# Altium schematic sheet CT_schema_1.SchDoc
size 515 x 464 mm
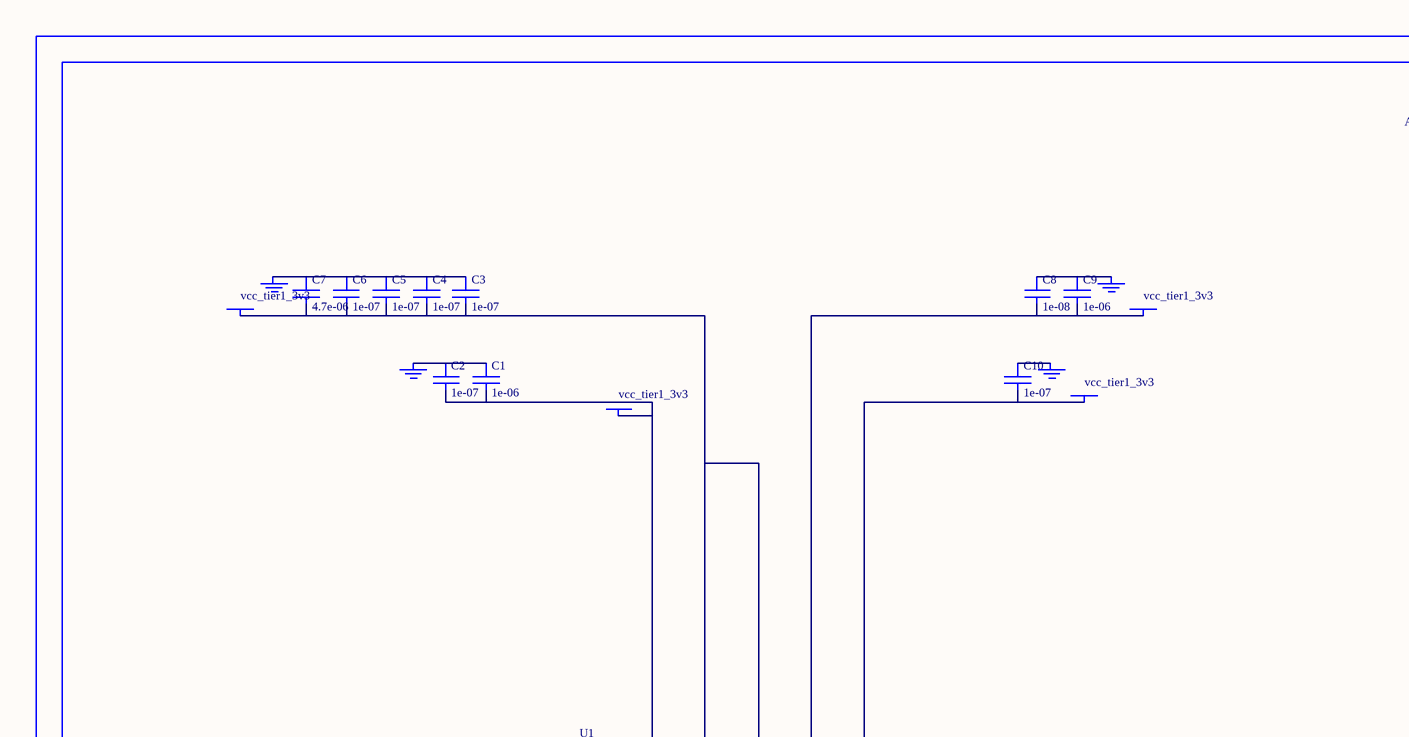
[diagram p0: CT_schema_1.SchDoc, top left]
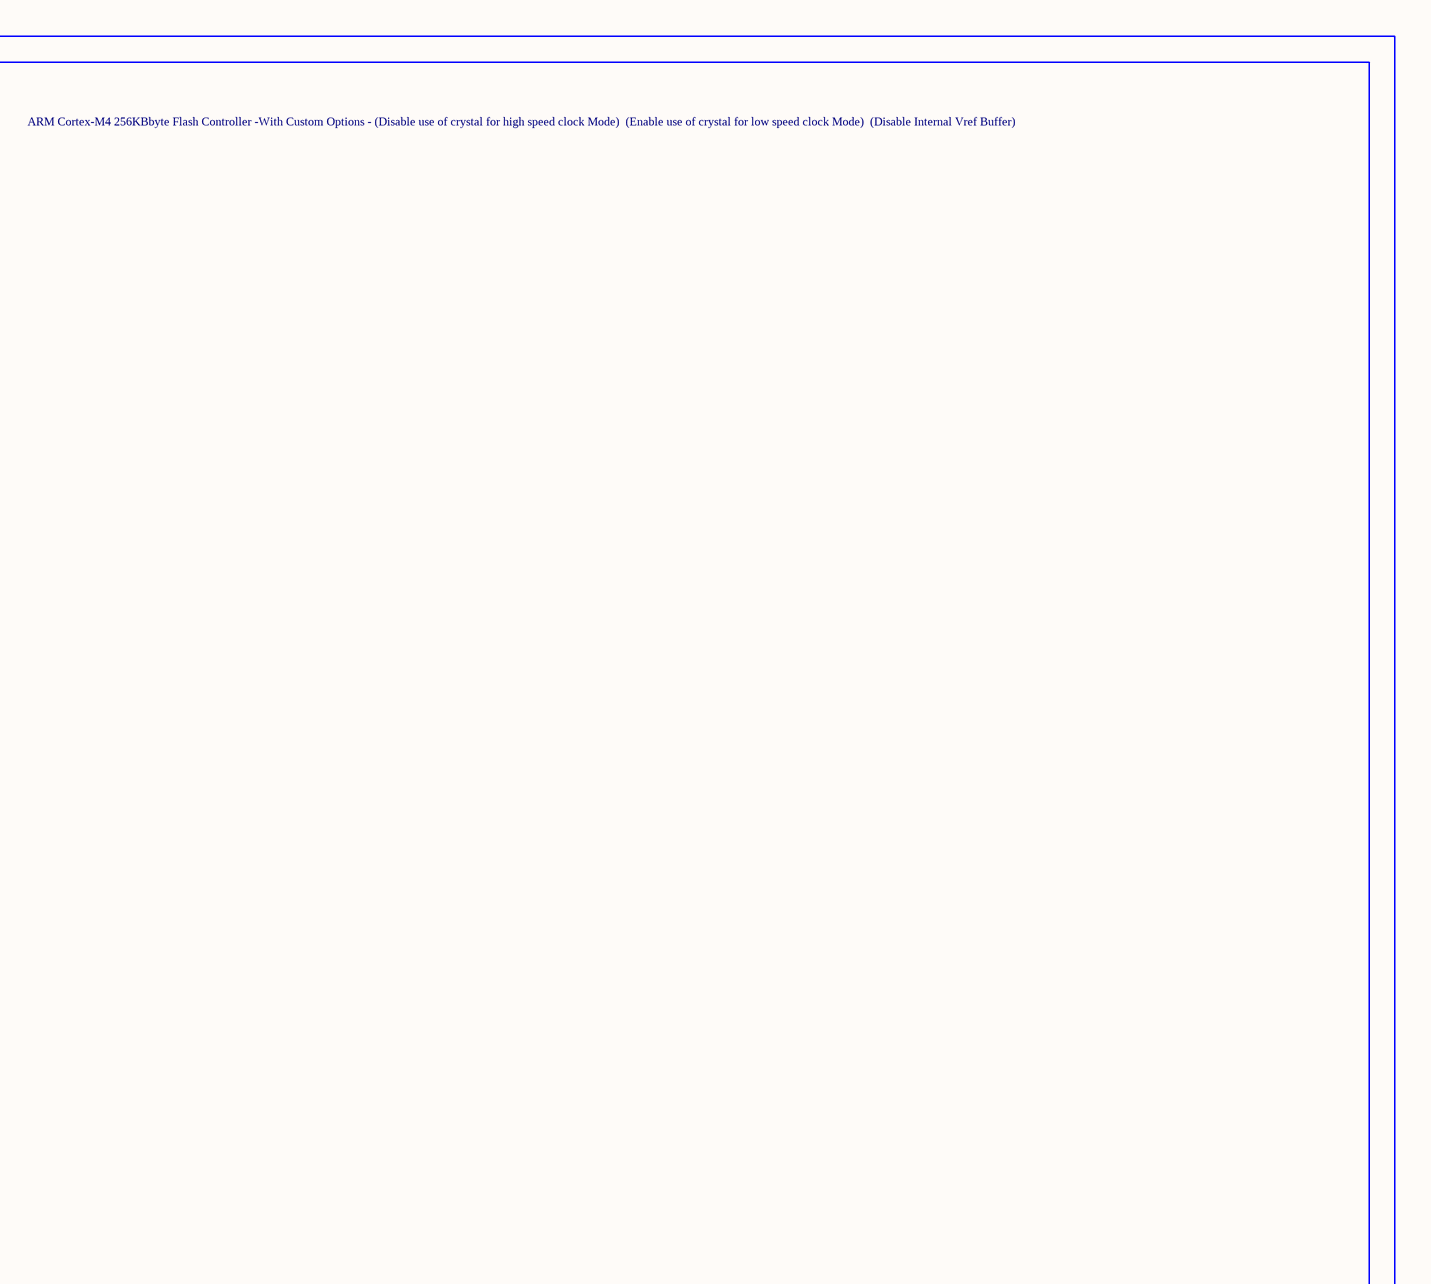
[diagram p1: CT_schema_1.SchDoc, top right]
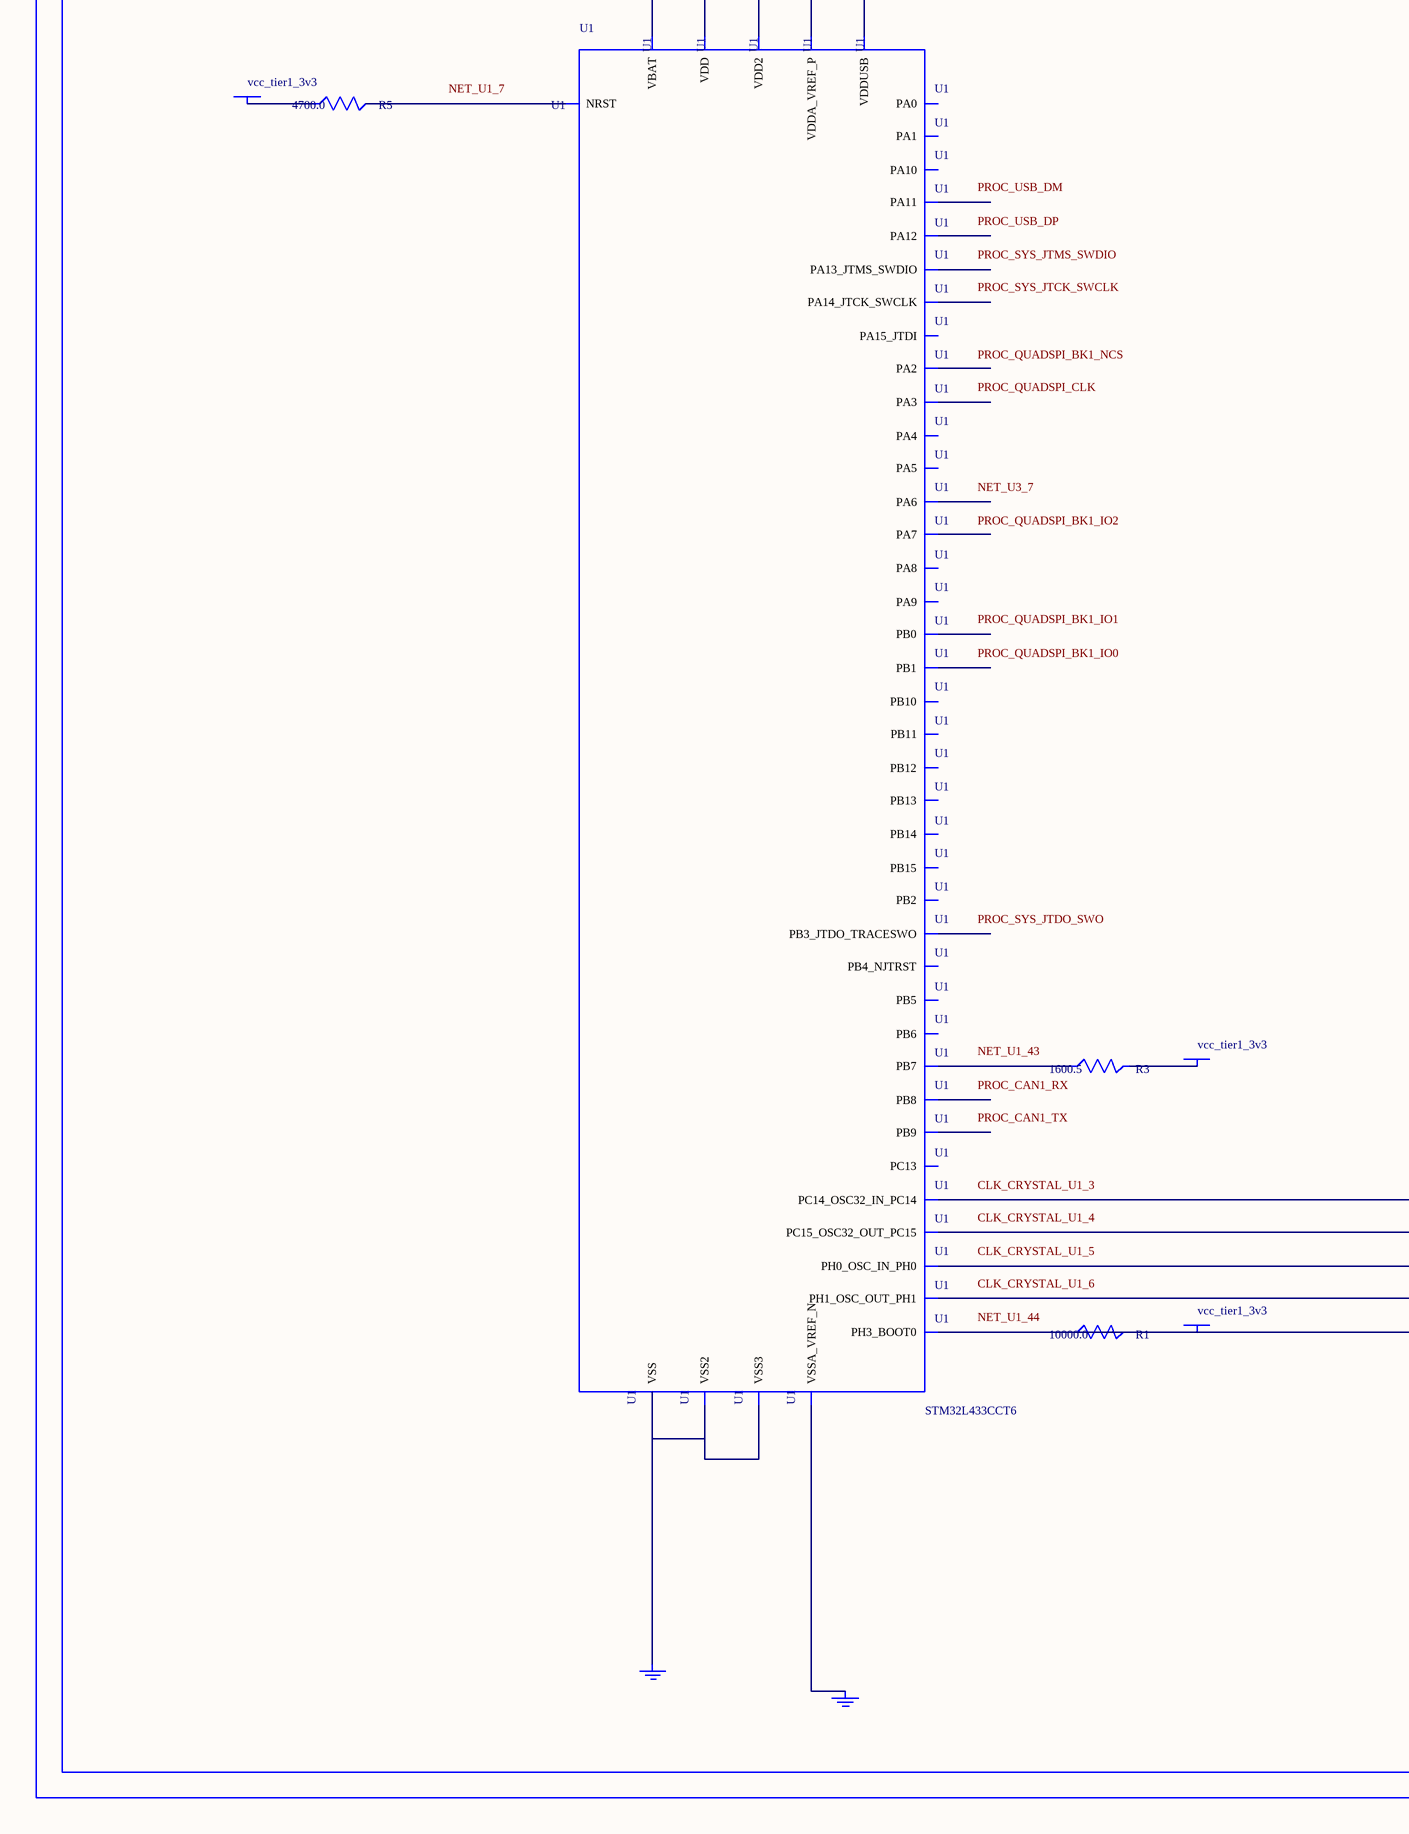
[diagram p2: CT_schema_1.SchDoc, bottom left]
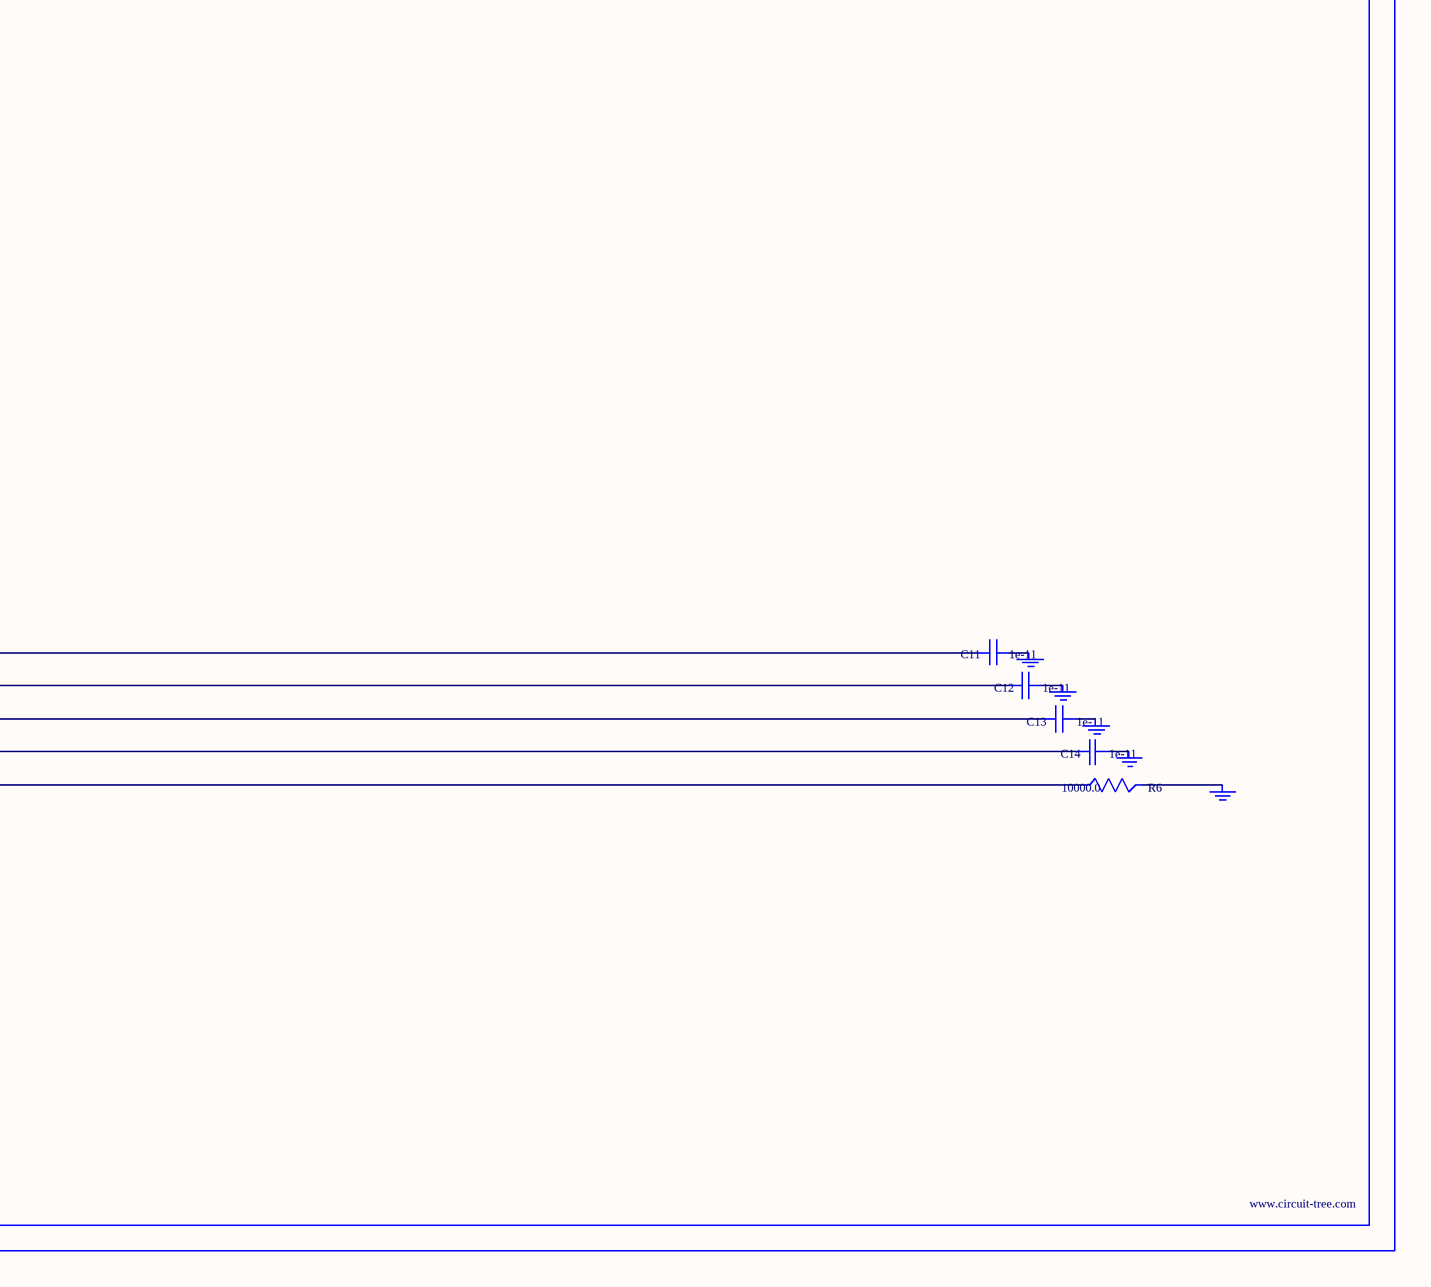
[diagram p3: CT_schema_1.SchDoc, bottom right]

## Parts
BORDER0  (no value)
C1  1e-06  [C0603]
C2  1e-07  [C0603]
C3  1e-07  [C0603]
C4  1e-07  [C0603]
C5  1e-07  [C0603]
C6  1e-07  [C0603]
C7  4.7e-06  [C0603]
C8  1e-08  [C0603]
C9  1e-06  [C0603]
C10  1e-07  [C0603]
C11  1e-11  [C0402]
C12  1e-11  [C0402]
C13  1e-11  [C0402]
C14  1e-11  [C0402]
GND_INSTANCE_0_0  (no value)
GND_INSTANCE_0_1  (no value)
GND_INSTANCE_0_2  (no value)
GND_INSTANCE_0_3  (no value)
GND_INSTANCE_0_4  (no value)
GND_INSTANCE_0_5  (no value)
GND_INSTANCE_0_6  (no value)
GND_INSTANCE_0_7  (no value)
GND_INSTANCE_0_8  (no value)
GND_INSTANCE_0_9  (no value)
GND_INSTANCE_0_10  (no value)
POWER_INSTANCE_0_0  vcc_tier1_3v3
POWER_INSTANCE_0_1  vcc_tier1_3v3
POWER_INSTANCE_0_2  vcc_tier1_3v3
POWER_INSTANCE_0_3  vcc_tier1_3v3
POWER_INSTANCE_0_4  vcc_tier1_3v3
POWER_INSTANCE_0_5  vcc_tier1_3v3
POWER_INSTANCE_0_6  vcc_tier1_3v3
R1  10000.0  [R0603]
R3  1600.5  [R0603]
R5  4700.0  [R0603]
R6  10000.0  [R0603]
U1  STM32L433CCT6  [LQFP48]

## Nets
NetC1_1: C1.1 C2.1 GND_INSTANCE_0_0.0(GND)
NetC1_2: C1.2 C2.2 POWER_INSTANCE_0_0.0(PWR) U1.1(VBAT)
NetC3_1: C3.1 C4.1 C5.1 C6.1 C7.1 GND_INSTANCE_0_7.0(GND)
NetC3_2: C3.2 C4.2 C5.2 C6.2 C7.2 POWER_INSTANCE_0_2.0(PWR) U1.24(VDD) U1.48(VDD2)
NetC8_1: C8.1 C9.1 GND_INSTANCE_0_6.0(GND)
NetC8_2: C8.2 C9.2 POWER_INSTANCE_0_1.0(PWR) U1.9(VDDA_VREF_P)
NetC10_1: C10.1 GND_INSTANCE_0_8.0(GND)
NetC10_2: C10.2 POWER_INSTANCE_0_3.0(PWR) U1.36(VDDUSB)
NetC11_1: C11.1 GND_INSTANCE_0_1.0(GND)
NetC11_2: C11.2 U1.3(PC14_OSC32_IN_PC14)
NetC12_1: C12.1 GND_INSTANCE_0_2.0(GND)
NetC12_2: C12.2 U1.4(PC15_OSC32_OUT_PC15)
NetC13_1: C13.1 GND_INSTANCE_0_3.0(GND)
NetC13_2: C13.2 U1.5(PH0_OSC_IN_PH0)
NetC14_1: C14.1 GND_INSTANCE_0_4.0(GND)
NetC14_2: C14.2 U1.6(PH1_OSC_OUT_PH1)
NetGND_INSTANCE_0_5_0: GND_INSTANCE_0_5.0(GND) U1.8(VSSA_VREF_N)
NetGND_INSTANCE_0_9_0: GND_INSTANCE_0_9.0(GND) R6.2
NetGND_INSTANCE_0_10_0: GND_INSTANCE_0_10.0(GND) U1.23(VSS) U1.35(VSS2) U1.47(VSS3)
NetPOWER_INSTANCE_0_4_0: POWER_INSTANCE_0_4.0(PWR) R5.1
NetPOWER_INSTANCE_0_5_0: POWER_INSTANCE_0_5.0(PWR) R3.2
NetPOWER_INSTANCE_0_6_0: POWER_INSTANCE_0_6.0(PWR) R1.1 R1.2 R6.1 U1.44(PH3_BOOT0)
NetR3_1: R3.1 U1.43(PB7)
NetR5_2: R5.2 U1.7(NRST)

Not connected (* = marked no-connect by the designer): U1 2(PC13) 10(PA0) 11(PA1) 12(PA2) 13(PA3) 14(PA4) 15(PA5) 16(PA6) 17(PA7) 18(PB0) 19(PB1) 20(PB2) 21(PB10) 22(PB11) 25(PB12) 26(PB13) 27(PB14) 28(PB15) 29(PA8) 30(PA9) 31(PA10) 32(PA11) 33(PA12) 34(PA13_JTMS_SWDIO) 37(PA14_JTCK_SWCLK) 38(PA15_JTDI) 39(PB3_JTDO_TRACESWO) 40(PB4_NJTRST) 41(PB5) 42(PB6) 45(PB8) 46(PB9)

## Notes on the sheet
- Labels drawn without touching a wire or pin: CLK_CRYSTAL_U1_3, CLK_CRYSTAL_U1_4, CLK_CRYSTAL_U1_5, CLK_CRYSTAL_U1_6, NET_U1_7, NET_U1_43, NET_U1_44, NET_U3_7, PROC_CAN1_RX, PROC_CAN1_TX, PROC_QUADSPI_BK1_IO0, PROC_QUADSPI_BK1_IO1, PROC_QUADSPI_BK1_IO2, PROC_QUADSPI_BK1_NCS, PROC_QUADSPI_CLK, PROC_SYS_JTCK_SWCLK, PROC_SYS_JTDO_SWO, PROC_SYS_JTMS_SWDIO, PROC_USB_DM, PROC_USB_DP

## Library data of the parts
BORDER0 = BORDER_PAGE0
C1 C9 = C0603C105K3RACTU
C2-C6 C10 = 06035C104K4Z2A
C7 = GRM188R6YA475KE15D
C8 = 06035C103K4Z2A
C11-C14 = C0402C100K3GACTU
GND_INSTANCE_0_0-GND_INSTANCE_0_10 = GND
POWER_INSTANCE_0_0-POWER_INSTANCE_0_6 = PWR
R1 R6 = RC0603JR-0710KL
R3 = R3
R5 = RC0603JR-074K7L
